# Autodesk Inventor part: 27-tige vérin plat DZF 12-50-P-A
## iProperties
Created: 2011-02
Part Number: 27-tige vérin plat DZF 12-50-P-A
Document SubType Name: Modeling
Designer: eric
Density: 1 g/cm^3
Author: eric
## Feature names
1. Base1
